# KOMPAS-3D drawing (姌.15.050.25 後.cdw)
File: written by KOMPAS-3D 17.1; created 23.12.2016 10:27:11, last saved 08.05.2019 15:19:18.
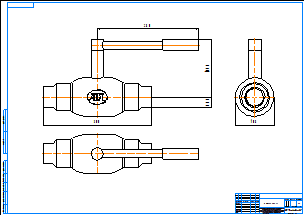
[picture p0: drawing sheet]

Sheet 1: A1, landscape

Title block, sheet 1: name: КШ.15.050.25 сс; material: Внимание! Данный продукт является объектом авторского права ООО «Торговый Дом АДЛ». / Запрещается изменение, копирование, распространение / (в том числе путем копирования на другие сайты и ресурсы в Интернете) / или любое иное использование информации и объектов без предварительного / согласия правообладателя (ООО «Торговый Дом АДЛ»).; sheets: 1; organisation: ООО "Торговый дом АДЛ"; sheet format: A1; stored path: C:\Users\tra\Desktop\2д чертежи\Шаровые краны БИВАЛ\КШ_Бивал_серия_14_15\KOMPAS_2D\КШ.15.050.25 сс.cdw

Views: Вид 1, Проекционный вид 2, Проекционный вид 3
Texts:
  Klimkovich
  ADL
Dimensions and other numbers on the sheet: 300; 280; 159,3; 28,5; 108; 1:1; 1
